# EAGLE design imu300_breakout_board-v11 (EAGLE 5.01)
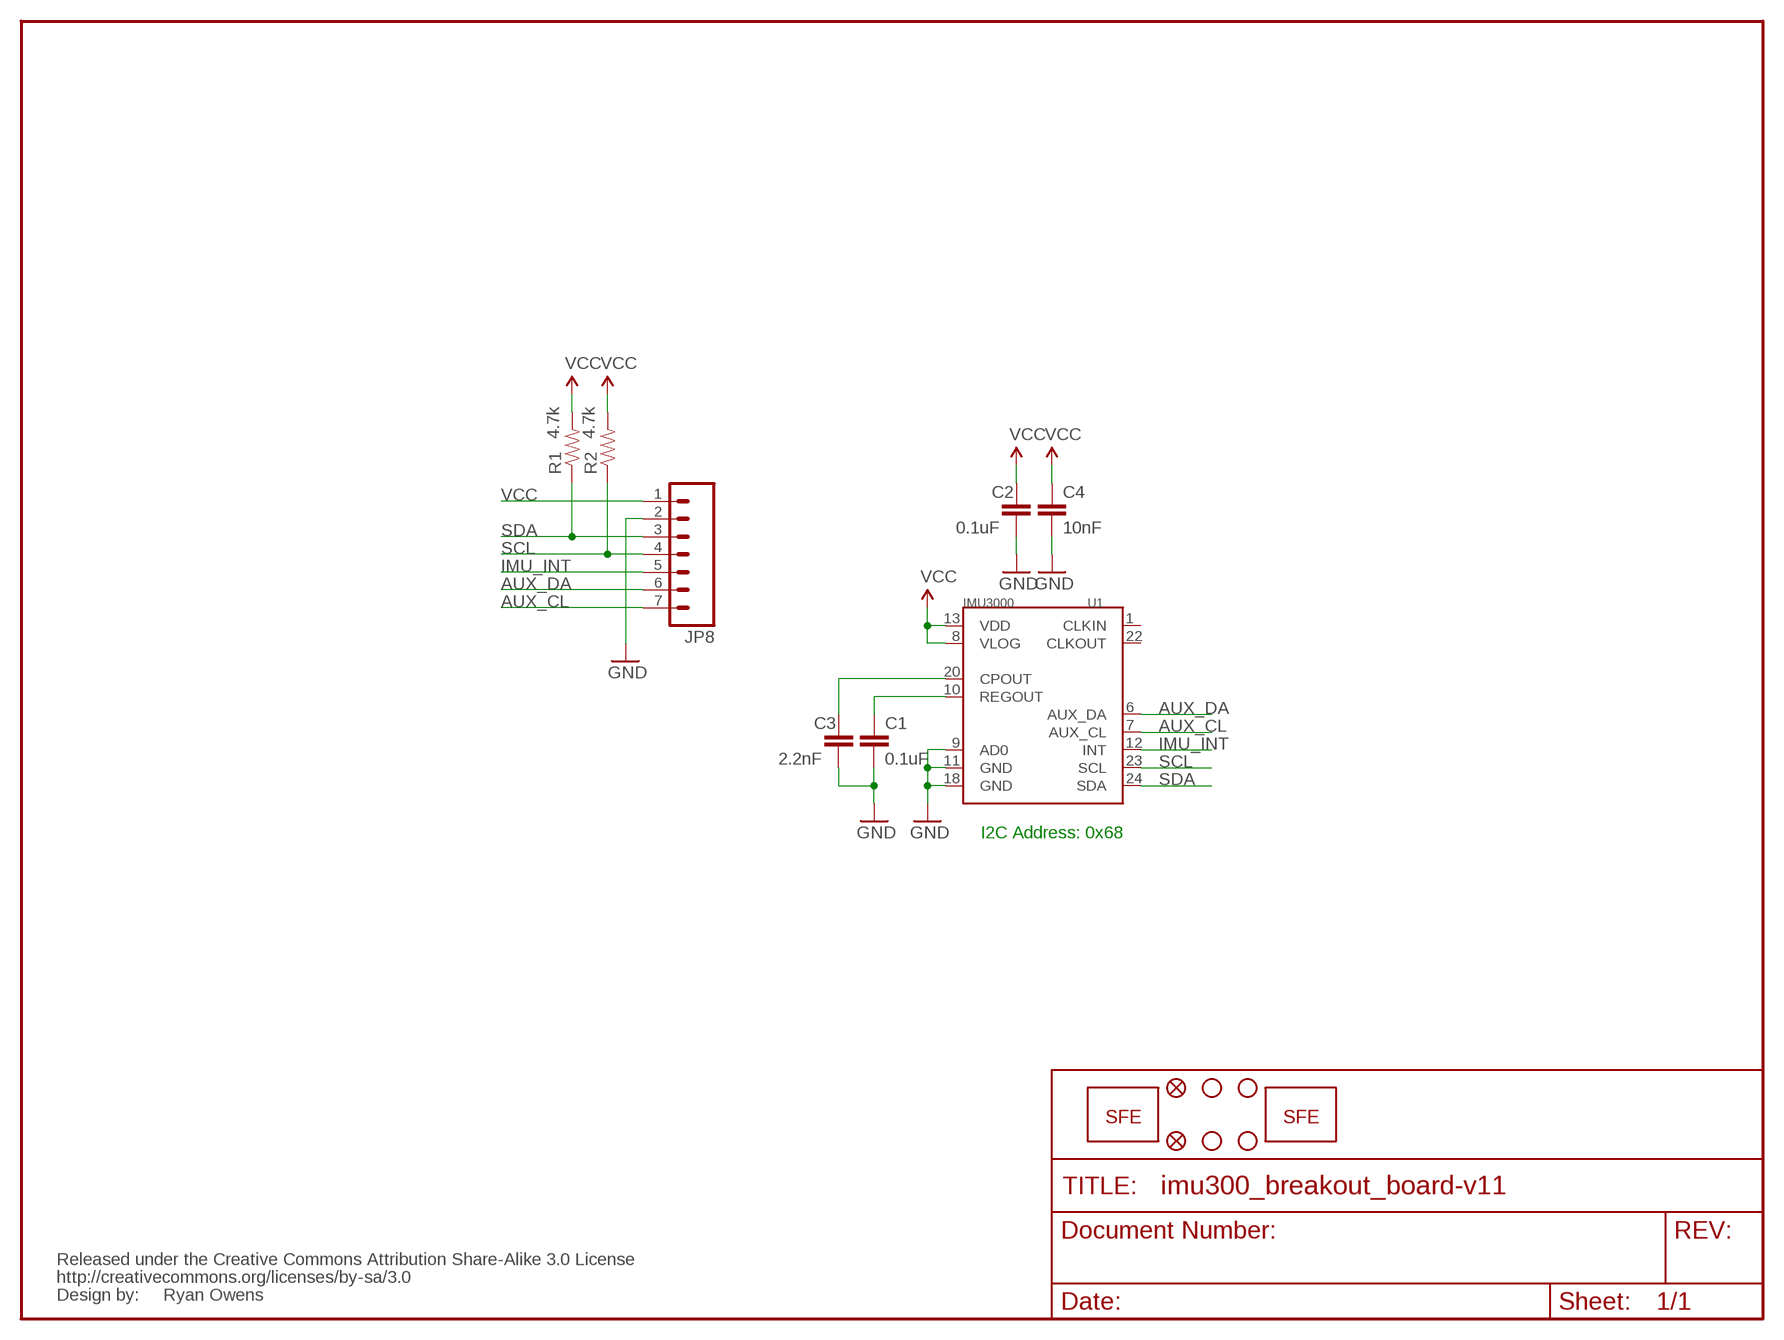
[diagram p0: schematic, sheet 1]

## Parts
C1  0.1uF  CAP0603-CAP  [0603-CAP]
C2  0.1uF  CAP0603-CAP  [0603-CAP]
C3  2.2nF  CAP0603-CAP  [0603-CAP]
C4  10nF  CAP0603-CAP  [0603-CAP]
JP1  LOGO-SFENEW  [SFE-NEW-WEBLOGO]
JP2  FIDUCIAL1X2  [FIDUCIAL-1X2]
JP3  FIDUCIAL1X2  [FIDUCIAL-1X2]
JP4  STAND-OFF  [STAND-OFF]
JP5  STAND-OFF  [STAND-OFF]
JP6  STAND-OFF  [STAND-OFF]
JP7  STAND-OFF  [STAND-OFF]
JP8  M07  [1X07]
JP9  LOGO-SFESK  [SFE-LOGO-FLAME]
R1  4.7k  RESISTOR0603-RES  [0603-RES]
R2  4.7k  RESISTOR0603-RES  [0603-RES]
U1  IMU3000  [QFN-24]
U$1  CREATIVE_COMMONS  [CREATIVE_COMMONS]

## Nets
AUX_CL: JP8.7 U1.7(AUX_CL)
AUX_DA: JP8.6 U1.6(AUX_DA)
GND: C1.2 C2.2 C3.2 C4.2 JP8.2 U1.9(AD0) U1.11(GND) U1.18(GND)
IMU_INT: JP8.5 U1.12(INT)
N$2: C3.1 U1.20(CPOUT)
N$4: C1.1 U1.10(REGOUT)
SCL: JP8.4 R2.1 U1.23(SCL)
SDA: JP8.3 R1.1 U1.24(SDA)
VCC: C2.1 C4.1 JP8.1 R1.2 R2.2 U1.8(VLOG) U1.13(VDD)
Unconnected: U1.1(CLKIN) U1.22(CLKOUT)

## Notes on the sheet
- I2C Address: 0x68
- Ryan Owens

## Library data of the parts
C1-C4 = SparkFun:CAP: Capacitor
JP1 JP9 = SparkFun:LOGO-SFE: Spark Fun Electronics PCB Logo
JP2 JP3 = SparkFun:FIDUCIAL: Fiducial Alignment Points
JP4-JP7 = SparkFun:STAND-OFF: Stand Off
JP8 = SparkFun:M07: Header 7 Standard 7-pin 0.1" header. Use with straight break away headers (SKU : PRT-00116), right angle break away headers (PRT-00553), swiss pins (PRT-00743), machine pins (PRT-00117), and female headers (PRT-00115). NOTES ON THE VARIANTS LOCK and LOCK_LONGPADS... This footprint was designed to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
R1 R2 = SparkFun:RESISTOR: Resistor
U1 = SparkFun:IMU3000
U$1 = SparkFun:CREATIVE_COMMONS

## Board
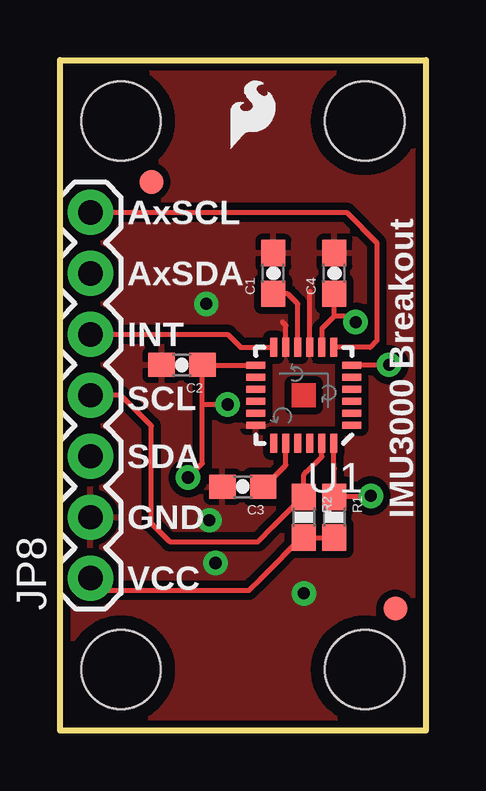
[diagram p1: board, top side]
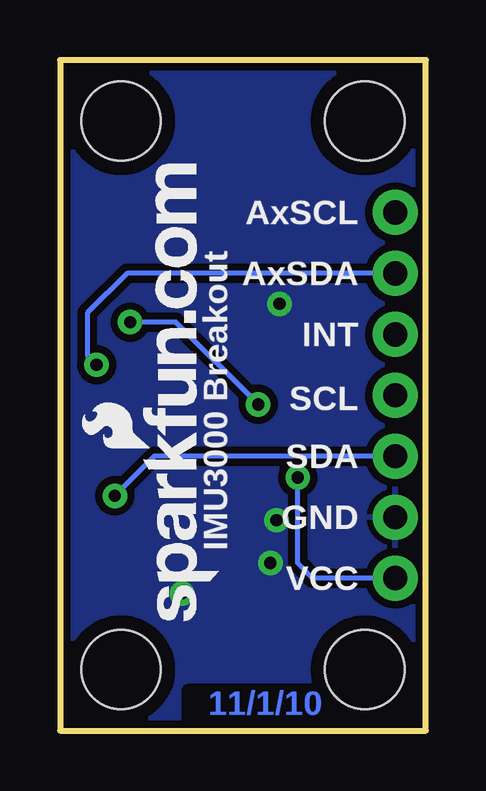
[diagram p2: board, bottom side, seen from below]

Size 15.24 x 27.94 mm. Coordinates in mm from the lower left corner, seen from the top.
Outline: 0,0 0,27.94 15.24,27.94 15.24,0 0,0
Copper layers (1*16): Top 0.035mm / dielectric 1.5mm / Bottom 0.035mm
Design rules "SparkFun *": minimum track width 8mil, minimum drill 20mil, track to track 8mil, track to pad 8mil, pad to pad 6mil, via to via 8mil, smd to smd 8mil, copper to edge 8mil, drill to drill 8mil, minimum pad ring 12mil, minimum via ring 10mil, stop-mask expansion 4mil, vias tented up to drill 20mil, thermal gap 10mil

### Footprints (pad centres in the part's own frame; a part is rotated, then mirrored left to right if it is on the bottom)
0603-CAP = smd 1.1 x 1: 1 -0.85,0; 2 0.85,0
FIDUCIAL-1X2 = smd 1 x 1: 1 0,0
STAND-OFF = hole 3.302: 0,0
1X07 = drill 1.016 pad 1.88 round: 1 0,0; 2 2.54,0; 3 5.08,0; 4 7.62,0; 5 10.16,0; 6 12.7,0; 7 15.24,0
0603-RES = smd 1.1 x 1: 1 -0.85,0; 2 0.85,0
QFN-24 = smd 0.8 x 0.3: 1 -2,1.25; 2 -2,0.75; 3 -2,0.25; 4 -2,-0.25; 5 -2,-0.75; 6 -2,-1.25; 13 2,-1.25; 14 2,-0.75; 15 2,-0.25; 16 2,0.25; 17 2,0.75; 18 2,1.25 | smd 0.3 x 0.8: 7 -1.25,-2; 8 -0.75,-2; 9 -0.25,-2; 10 0.25,-2; 11 0.75,-2; 12 1.25,-2; 19 1.25,2; 20 0.75,2; 21 0.25,2; 22 -0.25,2; 23 -0.75,2; 24 -1.25,2

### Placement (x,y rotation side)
C1  8.89,19.05 90 top
C2  5.08,15.24 180 top
C3  7.62,10.16 180 top
C4  11.43,19.05 90 top
JP1  8.64,4.57 90 bottom
JP2  13.97,5.08 0 top
JP3  3.81,22.86 0 top
JP4  2.54,2.54 0 top
JP5  2.54,25.4 0 top
JP6  12.7,2.54 0 top
JP7  12.7,25.4 0 top
JP8  1.27,6.35 90 top
JP9  7.11,24.26 0 top
R1  11.43,8.89 270 top
R2  10.16,8.89 270 top
U1  10.16,13.97 180 top
U$1  not placed on the board

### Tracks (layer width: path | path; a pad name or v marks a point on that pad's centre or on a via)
AUX_CL
  Top 0.203: U1.7 12.03,15.97 12.92,15.97 13.21,16.26 13.21,16.89 13.21,17.14 13.21,20.32 11.94,21.59 11.81,21.59 JP8.7
AUX_DA  (via drill 0.51)
  Top 0.203: U1.6 13.7,15.22 v13.72,15.24
  Bottom 0.203: JP8.6 12.45,19.05 14.1,17.4 14.1,15.62 v13.72,15.24
GND  (via drill 0.51)
  Top 0.203: U1.11 9.41,16.88 9.27,17.02 | U1.9 10.41,18.28 10.41,18.29
  other vias: 6.48,6.99 6.22,8.76 6.1,17.78 10.16,5.71
  pour Bottom (isolate 0.305): 0,0 0,27.94 15.24,27.94 15.24,0
  pour Top (isolate 0.305): 0,0 0,27.94 15.24,27.94 15.24,0
IMU_INT
  Top 0.203: JP8.5 6.99,16.51 7.24,16.26 7.37,16.13 7.53,15.97 U1.12
N$2
  Top 0.203: C3.1 8.51,10.16 9.41,11.06 U1.20
N$4
  Top 0.203: U1.10 9.91,17.78 9.65,18.03 9.49,18.2 C1.1
SCL
  Top 0.203: U1.23 10.91,11.42 10.29,10.79 10.16,10.67 R2.1 10.12,9.74 8.89,8.51 8.26,7.87 4.57,7.87 3.81,8.64 3.81,12.7 2.54,13.97 JP8.4
SDA  (via drill 0.51)
  Top 0.203: U1.24 11.41,10.94 11.43,10.92 R1.1 12.91,9.74 v12.95,9.78
  Bottom 0.203: JP8.3 11.3,11.43 v12.95,9.78
VCC  (via drill 0.51)
  Top 0.203: R1.2 11.34,8.04 11.3,8 11.26,8.04 R2.2 10.16,8.13 8.38,6.35 7.87,5.84 6.86,5.84 1.78,5.84 JP8.1 | U1.8 10.91,16.75 11.3,17.14 11.43,17.27 | 11.43,17.27 C4.1 | 5.93,13.59 5.93,11.14 5.71,10.92 v5.33,10.54 | 5.93,13.59 C2.1 5.97,15.24 5.99,15.22 U1.13 | 5.93,13.59 6.1,13.59 v6.99,13.59 | 11.43,17.27 12.06,17.27 v12.32,17.02
  Bottom 0.203: v5.33,10.54 5.33,10.41 5.33,6.99 4.7,6.35 JP8.1 | v12.32,17.02 10.41,17.02 v6.99,13.59

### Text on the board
Bottom: 11/1/10
tPlace: AxSCL | IMU3000 Breakout | AxSDA | INT | SCL | SDA | GND | VCC
bPlace: AxSCL | AxSDA | INT | SCL | SDA | GND | VCC | IMU3000 Breakout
